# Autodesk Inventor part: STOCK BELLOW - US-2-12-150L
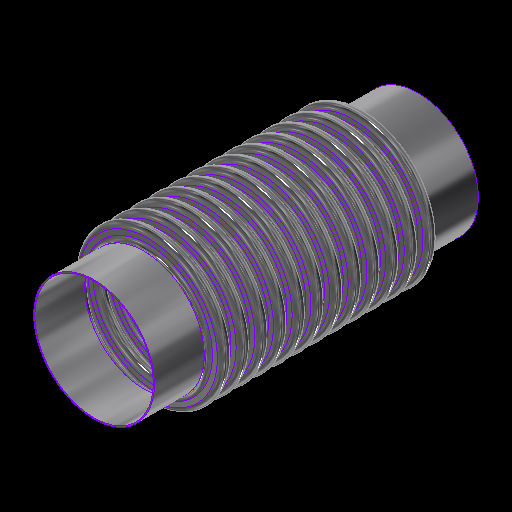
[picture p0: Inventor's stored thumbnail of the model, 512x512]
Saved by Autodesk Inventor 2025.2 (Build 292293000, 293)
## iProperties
Category: 24 GA (0.024 THICK)
RuleStatus: InUse
Created: 2024-01
Part Number: STOCK BELLOW - US-2-12-150L
Project: =STOCK BELLOWS: <Stock Number><SFILL>
Material: ASTM A240-304
Description: =STOCK BELLOWS: <Stock Number>, <SID_> I.D., <SOD_> O.D., <SPLY_> PLY, <Category>, <SNET_CONS> CONS.<PITCH_><STANGENT_> TANGENT<SFILL>
Document SubType Name: Sheet Metal
Designer: GS
Stock Number: U.S-2-12-150L
Surface Area: 1235.64 cm^2
Volume: 37.4488 cm^3
Sheet Metal Rule: Default
Appearance: STAINLESS STEEL
Mass: 301.736 g
Density: 8.05729 g/cm^3
THK: 0.036
ID: 3.500
OD: 4.250
CONS_: 2
PITCH: 0.500
TANGENT: 0.500
BELLOWS_UPSET: 0.000
d79: 1.000
d82: 1.000
d83: 26.000
d84: 24.000
d174: 8
d214: 8
STHK_: 0.024
SID_: 2.375
SOD_: 3.000
SPITCH_: 0.375
STANGENT__: 1.000
SBELLOWS_UPSET_: 0.000
SDIFF_TAN: 1.000
d252: 2
d275: 2
d287: 0.050
d289: 0.500
d290: 0.000
SOD_NECK: 2 7/16
PLY: 1
PSET: 4.178
PBAR: 1.035
COUNTER: 1.500
NET_TUBE: 3.071
CONS: 2
S_CONS: 0
NET_CONS: 2
ID_M: 88.90 mm
OD_M: 107.95 mm
THK_M: 0.91 mm
ID_U: 3.500 in
OD_U: 4.250 in
THK_U: 0.036 in
TANGENT2: 0.500
TAN_TO_TAN: 1.000 in
d80: 2.571
d81: 10
SID: 2.375
SCONS_: 12
SPITCH: 0.250
STANGENT_: 1.000
SBELLOWS_UPSET: 0.000
SNET_CONS: 12
SS_CONS: 0
SCONS: 8
d190: 8
d191: 1
d192: 1
d193: 8
d194: 0
SIZE: 2.00
PRESSURE: 150
d230: 8
STANGENT: 4.000
SPLY_: 1
d233: 8
d234: 0
d263: 2
d265: 1
d268: 2
d269: 0
d286: 2
d288: 1
d291: 2
d292: 0
SREROLL: 0.750
BLETP: 1.000 ul
PRES_Copy: 85
MATTABLE: 20 GA (0.036 THICK)
PART_NUMBER: U.S-2-12-150L
PITCH_: =, <SPITCH_> PITCH,
CFILL: .
SFILL: .
MESH: ,
COMP: 0.51
EXT: 0.26
LAT: 0.28
ANG: 573
ASR: 1940
LSR: 934
ANSR: 28
PRES: 150
COMPM: 5.1
EXTM: 2.55
LATM: 2.80
ASRM: 339.752
PRESM: 10.342
LSRM: 163.571
ANSRM: 4.904
TEMPMIN: 20
TEMPMAX: 800
TEMPMINM: -7
TEMPMAXM: 427
WEIGHTM: 0.302
WEIGHT: 0.665
Author: GS
Keywords: 20 GA (0.036 THICK)
Comments: =STOCK BELLOW - <STOCK NUMBER>
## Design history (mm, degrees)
sketch "Sketch2"
  geometry: L1 (0, -177.245)-(0, 562.856) reference; L2 (45.364, 0)-(44.45, 0); L3 (48.082, -2.718)-(50.343, -2.718); L4 (48.082, -3.632)-(50.343, -3.632); L5 (50.343, -9.982)-(48.082, -9.982); L6 (50.343, -9.068)-(48.082, -9.068); L7 (45.364, -12.7)-(44.45, -12.7); L8 (48.082, 0)-(48.082, -12.7); L9 (50.343, -6.35)-(53.975, -6.35); L10 (44.45, 0)-(44.45, -12.7); L11 (20.376, 102.841)-(20.376, 101.926); L12 (58.262, 457.127)-(58.262, 349.177); L13 (58.262, 444.427)-(58.262, 336.477); L14 (93.133, -58.817)-(93.133, -71.517); L15 (118.746, -66.401)-(118.746, -66.401); L16 (50.343, -9.068)-(50.343, -9.982); L17 (48.082, -9.068)-(48.082, -9.982); L18 (48.082, -9.525)-(50.343, -9.525); L19 (53.975, 0)-(53.975, -12.7); L20 (-50.343, -9.068)-(-50.343, -9.982); L21 (-50.343, -2.718)-(-48.082, -2.718); L22 (-50.343, -3.632)-(-48.082, -3.632); L23 (-48.082, -9.068)-(-50.343, -9.068); L24 (-50.343, -9.525)-(-48.082, -9.525); L25 (-48.082, -9.982)-(-50.343, -9.982); L26 (-48.082, -9.068)-(-48.082, -9.982); L27 (-44.45, 0.653)-(-44.45, -12.047); L28 (-48.082, -6.35)-(-44.45, -6.35); L29 (-50.343, 0.653)-(-50.343, -12.7); L30 (-53.061, 0)-(-53.975, 0); L31 (-53.975, 0)-(-53.975, -12.7); L32 (-53.061, -12.7)-(-53.975, -12.7); A1 r 2.718 centre (48.082, 0) between (45.364, 0) and (48.082, -2.718); A2 r 3.632 centre (48.082, 0) between (44.45, 0) and (48.082, -3.632); A3 r 3.632 centre (50.343, -6.35) between (50.343, -9.982) and (50.343, -2.718); A4 r 2.718 centre (50.343, -6.35) between (50.343, -9.068) and (50.343, -3.632); A5 r 2.718 centre (48.082, -12.7) between (48.082, -9.982) and (45.364, -12.7); A6 r 3.632 centre (48.082, -12.7) between (48.082, -9.068) and (44.45, -12.7); A7 r 3.175 centre (50.343, -6.35) between (50.343, -9.525) and (53.518, -6.35); A8 r 3.175 centre (48.082, -12.7) between (48.082, -9.525) and (44.907, -12.7); A9 r 2.718 centre (-50.343, -12.7) between (-50.343, -9.982) and (-53.061, -12.7); A10 r 2.718 centre (-48.082, -6.35) between (-48.082, -9.068) and (-48.082, -3.632); A11 r 3.175 centre (-48.082, -6.35) between (-48.082, -9.525) and (-44.907, -6.35); A12 r 3.632 centre (-48.082, -6.35) between (-48.082, -9.982) and (-48.082, -2.718); A13 r 3.175 centre (-50.343, -12.7) between (-50.343, -9.525) and (-53.518, -12.7); A14 r 3.632 centre (-50.343, -12.7) between (-50.343, -9.068) and (-53.975, -12.7); A15 r 2.718 centre (-50.343, 0) between (-53.061, 0) and (-50.343, -2.718); A16 r 3.632 centre (-50.343, 0) between (-53.975, 0) and (-50.343, -3.632); 10 further points
  constraints: 62 end point, 38 point on circle, 20 tangent, 16 centre point, 12 parallel, 9 midpoint, 7 vertical, 6 coincident, 6 concentric, 6 point on line, 4 equal radius, 4 perpendicular, 3 horizontal, 1 collinear, 1 horizontal alignment, 10 other
  dimensions: "THK" = 0.9144 distance of L11.start L11.end; "ID" = 88.9 distance of L11.end point (20.376, 13.026); "OD" = 107.95 distance of L12.start L12.end; "PITCH" = 12.7 distance of L12.start L13.start; "TANGENT" = 12.7 distance of L14.start L14.end; "BELLOWS_UPSET" = 0 distance of L15.start L15.end; "d43" = 88.9 diameter of L10 L1 (= ID); "d44" = 107.95 diameter of L9.end L1 (= OD); "d45" = 0.9144 distance between parallel lines of L5 L6 (computed from THK, PLY); "d46" = 3.6322 radius of A3 (computed from PITCH, THK, PLY); "UPSET_PITCH" = 12.7 distance of L2.end L7.end (derived); "SIDEWALL_ANGLE" = 360 deg dimension on L3 L9 (derived); "CON_GAP" = 5.4356 distance of point (48.082, -9.068) point (48.082, -3.632) (derived); "TAN1" = 4.98728 dimension on A8 (derived); "TAN2" = 4.98728 dimension on A7 (derived); "LEG1" = 2.2606 distance of L18.start L18.end (derived); "d278" = 0.9144 distance between parallel lines of L25 L23 (derived); "d279" = 3.6322 radius of A12 (derived); "d280" = 12.7 distance of L30.end L31.end (derived); "d281" = 360 deg dimension on L21 L28 (derived); "d282" = 5.4356 distance of point (-50.343, -9.068) point (-50.343, -3.632) (derived); "d283" = 4.98728 dimension on A13 (derived); "d284" = 4.98728 dimension on A11 (derived); "d285" = 2.2606 distance of L24.start L24.end (derived); "d293" = 88.9 diameter of L27 L1 (derived); "d294" = 107.95 diameter of L31 L1 (derived)
  node "Sketch Rectangular Pattern1" dims "d31" = 25.4, "ID" = 88.9
  node "Sketch Rectangular Pattern2" dims "d39" = 25.4, "PITCH" = 12.7
revolve "CONS" stored, may be unused: angle "d48" = 90 deg
node "BELLOW MIDPLANE"
pattern_linear "Rectangular Pattern2" dims "d52" = 12.7 (= UPSET_PITCH)
sketch "Sketch5"
  geometry: C1 r 45.364 at (0, 0) reference; C2 r 44.45 at (0, 0) reference
extrude "TANGENT" new body sketch "Sketch5" distance "d53" = 12.7 (= TANGENT); taper "d54" = 0 deg
revolve "SAMETAN" stored, may be unused: angle "d65" = 90 deg
revolve "DIFFTAN" stored, may be unused: angle "d70" = 90 deg
sketch "Sketch9"
  geometry: L1 (53.319, 0)-(-53.319, 0) reference; L2 (0, -17.78)-(0, 17.78) reference; L3 (38.085, 0)-(-38.085, 0); L4 (38.085, -11.906)-(38.085, 11.906); L5 (25.385, -11.906)-(25.385, 11.906); L6 (13.15, 11.906)-(13.15, -11.906); L7 (-25.385, -11.906)-(-25.385, 11.906); L8 (-38.085, -11.906)-(-38.085, 11.906); L9 (37.291, -11.906)-(37.291, 11.906); L10 (38.085, -11.906)-(37.291, -11.906); L11 (38.085, 11.906)-(37.291, 11.906); L12 (13.546, 11.906)-(12.753, 11.906); L13 (12.753, 11.906)-(12.753, -11.906); L14 (12.753, -11.906)-(13.546, -11.906); L15 (13.546, -11.906)-(13.546, 11.906); L16 (-13.546, 11.906)-(-13.546, -11.906); L17 (-13.15, 11.906)-(-13.15, -11.906); L18 (-13.546, -11.906)-(-12.753, -11.906); L19 (-12.753, -11.906)-(-12.753, 11.906); L20 (-12.753, 11.906)-(-13.546, 11.906); L21 (-38.085, -11.906)-(-37.291, -11.906); L22 (-37.291, -11.906)-(-37.291, 11.906); L23 (-37.291, 11.906)-(-38.085, 11.906); L24 (-38.085, 11.906)-(-38.085, -11.906); L25 (38.085, -0.397)-(-38.085, -0.397); L26 (-38.085, -0.397)-(-38.085, 0.397); L27 (-38.085, 0.397)-(38.085, 0.397); L28 (38.085, 0.397)-(38.085, -0.397); L29 (-38.085, 11.906)-(38.085, 11.906); L30 (38.085, 11.906)-(38.085, 12.7); L31 (38.085, 12.7)-(-38.085, 12.7); L32 (-38.085, 12.7)-(-38.085, 11.906); L33 (38.085, -11.906)-(-38.085, -11.906); L34 (-38.085, -11.906)-(-38.085, -12.7); L35 (-38.085, -12.7)-(38.085, -12.7); L36 (38.085, -12.7)-(38.085, -11.906); 30 further points
  constraints: 68 end point, 13 midpoint, 13 parallel, 8 horizontal, 7 perpendicular, 6 equal length, 3 point on line, 2 vertical, 14 other
  dimensions: "d115" = 23.8125 distance of L4.start L4.end (derived); "d116" = 12.7 distance between parallel lines of L4 L5 (derived); "d117" = 12.23516 distance between parallel lines of L5 L6 (derived); "d125" = 38.53427 distance between parallel lines of L7 L6 (derived); "d127" = 12.7 distance between parallel lines of L8 L7 (derived); "d128" = 24.93516 distance between parallel lines of L6 L4 (derived); "d130" = 76.16943 distance between parallel lines of L8 L4 (derived); "RULER_THK" = 0.79375 distance between parallel lines of L4 L9; "d135" = 0.79375 distance of L13.end L14.end (derived); "d138" = 26.29911 distance of L13.end L16.end (derived); "d143" = 0.79375 distance of L22.end L8.end (derived); "d144" = 0.79375 distance between parallel lines of L27 L25 (derived)
extrude "RULER" join sketch "Sketch9" distance "d149" = 0.79375 (derived); taper "d150" = 0 deg
extrude "BARS" join sketch "Sketch9" distance "d151" = 0.79375 (derived); taper "d152" = 0 deg
pattern_linear "Rectangular Pattern4" dims "d155" = 26.29911 (derived)
sketch "Sketch13"
  geometry: L1 (93.149, -52.467)-(93.149, -77.867); L2 (30.772, 0)-(30.162, 0); L3 (30.772, -9.525)-(30.162, -9.525); L4 (35.414, -7.449)-(32.849, -7.449); L5 (35.414, -6.839)-(32.849, -6.839); L6 (35.414, -4.763)-(38.1, -4.762); L7 (32.849, -2.076)-(35.414, -2.076); L8 (32.849, 0)-(32.849, -9.525); L9 (30.162, 0)-(30.162, -9.525); L10 (58.254, -420.231)-(58.254, -496.431); L11 (58.254, -429.756)-(58.254, -505.956); L12 (58.254, -448.806)-(58.254, -525.006); L13 (58.254, -458.331)-(58.254, -534.531); L14 (58.254, -467.856)-(58.254, -544.056); L15 (58.254, -477.381)-(58.254, -553.581); L16 (58.254, -486.906)-(58.254, -563.106); L17 (58.254, -439.281)-(58.254, -515.481); L18 (20.376, 102.536)-(20.376, 101.926); L19 (32.849, -2.686)-(35.414, -2.686); L20 (0, -696.234)-(0, 235.664) reference; L21 (-23.752, 0)-(142.514, 0) reference; A1 r 2.076 centre (32.849, 0) between (30.772, 0) and (32.849, -2.076); A2 r 2.076 centre (32.849, -9.525) between (32.849, -7.449) and (30.772, -9.525); A3 r 2.686 centre (32.849, -9.525) between (32.849, -6.839) and (30.162, -9.525); A4 r 2.076 centre (35.414, -4.763) between (35.414, -6.839) and (35.414, -2.686); A5 r 2.686 centre (35.414, -4.763) between (35.414, -7.449) and (35.414, -2.076); A6 r 2.686 centre (32.849, 0) between (30.162, 0) and (32.849, -2.686); 6 further points; 1 other entity
  constraints: 38 end point, 15 point on circle, 9 tangent, 6 centre point, 6 parallel, 5 vertical alignment, 4 point on line, 4 vertical, 3 coincident, 3 concentric, 2 collinear, 2 equal radius, 1 horizontal, 1 perpendicular, 23 other
  dimensions: "SBELLOWS_UPSET_" = 0 distance of point (118.762, -66.401) point (118.762, -66.401); "STOTAL_THK_BELLOW__" = 0.6096 distance between parallel lines of L4 L5 (derived); "d224" = 2.68605 radius of A5 (derived); "d225" = 9.525 distance of L2.end L3.end (derived); "SSIDEWALL_ANGLE_" = 0 deg angle of L7 L6 (derived); "SSCON_GAP_" = 4.1529 distance of point (32.849, -6.839) point (32.849, -2.686) (derived); "d235" = 60.325 diameter of L9 L20 (derived); "d236" = 76.2 diameter of L6.end L20 (derived)
  node "Sketch Rectangular Pattern4" dims "d228" = 25.4
  node "Sketch Rectangular Pattern5" dims "d229" = 25.4
revolve "SBELLOW" stored, may be unused: angle "d197" = 90 deg
pattern_linear "Rectangular Pattern5" dims "d204" = 9.525 (derived)
revolve "STANGENT" stored, may be unused: angle "d240" = 90 deg
revolve "SSAMETAN" stored, may be unused: angle "d241" = 90 deg
revolve "SDIFFTAN" stored, may be unused: angle "d246" = 90 deg
revolve "INVCON" stored, may be unused: angle "d295" = 90 deg
pattern_linear "Rectangular Pattern6" dims "d298" = 12.7 (derived)
revolve "INVTANGENT" stored, may be unused: angle "d302" = 90 deg
revolve "INVSAMETAN" stored, may be unused: angle "d307" = 90 deg
revolve "INVDIFFTAN" stored, may be unused: angle "d312" = 90 deg
sketch "ID BELLOW MOUNT CALC"
  geometry: L1 (44.45, 0)-(38.1, 0); L2 (38.1, 0)-(38.1, 12.7); L3 (38.1, 12.7)-(44.45, 12.7); L4 (44.45, 12.7)-(44.45, 0); L5 (36.513, 12.7)-(35.598, 12.7); L6 (35.598, 12.7)-(35.598, 0); L7 (35.598, 0)-(36.513, 0); L8 (36.513, 0)-(36.513, 12.7); L9 (0, -2.54)-(0, 15.24) reference; L10 (-8.89, 0)-(53.34, 0) reference; 1 further point
  constraints: 16 end point, 5 parallel, 2 collinear, 2 horizontal, 2 perpendicular
  dimensions: "d314" = 12.7 distance of L5.end L6.end (derived); "d315" = 0.9144 distance of L5.start L5.end (derived); "IG" = 1.5875 distance between parallel lines of L2 L8; "PIPE_OD" = 88.9 diameter of L4 L9; "PIPE_WALL" = 6.35 distance of L2.end L3.end; "ID_MT_BELLOW" = 71.1962 diameter of L6 L9 (derived)
revolve "CFILL" stored, may be unused: angle "d320" = 90 deg
pattern_linear "Rectangular Pattern7" dims "d323" = 12.7 (derived)
revolve "SFILL" stored, may be unused: angle "d324" = 90 deg
pattern_linear "Rectangular Pattern8" dims "d327" = 9.525 (derived)
node "STOCK BELLOW MIDPLANE"
node "BELLOW"
sketch "Sketch6"
  geometry: L1 (-12.7, 45.364)-(0, 45.364); L2 (0, 45.364)-(0, 44.45); L3 (0, 44.45)-(-12.7, 44.45); L4 (-12.7, 44.45)-(-12.7, 45.364); L5 (10.16, 0)-(-60.96, 0) reference; L6 (-38.1, -89.422)-(-38.1, 153.44) reference; 1 further point
  constraints: 8 end point, 2 parallel, 1 horizontal, 1 perpendicular
  dimensions: "d61" = 12.7 distance of L2.end L3.end (derived); "d62" = 0.9144 distance of L1.end L2.end (derived); "d63" = 88.9 diameter of L3 L5 (derived); "d64" = 25.4 distance between parallel lines of L4 L6 (derived)
sketch "Sketch12"
  geometry: 1 further point
sketch "Sketch14"
  geometry: L1 (-25.4, 30.772)-(0, 30.772); L2 (0, 30.772)-(0, 30.162); L3 (0, 30.162)-(-25.4, 30.162); L4 (-25.4, 30.162)-(-25.4, 30.772); L5 (5.08, 0)-(-30.48, 0) reference; L6 (0, -8.89)-(0, 53.34) reference; 1 further point
  constraints: 8 end point, 2 parallel, 1 collinear, 1 horizontal, 1 perpendicular
  dimensions: "d237" = 0.6096 distance of L3.end L1.start (derived); "d238" = 60.325 diameter of L3 L5 (derived); "d239" = 25.4 distance of L1.start L1.end (derived); "SOD_NECK" = 61.5442 diameter of L1 L5 (derived)
sketch "Sketch15"
  geometry: L1 (-8.89, 0)-(53.34, 0) reference; L2 (30.163, -114.3)-(30.772, -114.3); L3 (30.772, -114.3)-(30.772, -139.7); L4 (30.772, -139.7)-(30.163, -139.7); L5 (30.163, -139.7)-(30.163, -114.3); L6 (0, -170.18)-(0, 43.18) reference; 1 further point
  constraints: 8 end point, 2 parallel, 1 horizontal, 1 perpendicular
  dimensions: "d205" = 25.4 distance of L4.end L2.start (derived); "d206" = 0.6096 distance of L3.end L4.end (derived); "d207" = 60.325 diameter of L5 L6 (derived); "d208" = 114.3 distance between parallel lines of L1 L2 (derived)
node "TANGENT_"
node "SAME_TAN"
sketch "Sketch8"
  geometry: L1 (45.364, -25.4)-(44.45, -25.4); L2 (44.45, -25.4)-(44.45, -38.1); L3 (44.45, -38.1)-(45.364, -38.1); L4 (45.364, -38.1)-(45.364, -25.4); L5 (0, -48.26)-(0, 22.86) reference; L6 (-89.422, 0)-(153.44, 0) reference; 1 further point
  constraints: 8 end point, 2 parallel, 1 horizontal, 1 perpendicular
  dimensions: "d66" = 88.9 diameter of L2 L5 (derived); "TOTAL_THK_BELLOW" = 0.9144 distance of L2.end L3.end (derived); "d68" = 25.4 distance between parallel lines of L1 L6 (derived); "d69" = 12.7 distance of L1.end L2.end (derived)
node "DIFF_TAN"
node "Sketch Rectangular Pattern3" dims "d138" = 26.29911 (derived), "d141" = 25.4
node "SBELLOW_"
node "STANGENT_"
node "SSAME_TAN"
sketch "Sketch16"
  geometry: L1 (30.772, -114.3)-(30.163, -114.3); L2 (30.163, -114.3)-(30.163, -139.7); L3 (30.163, -139.7)-(30.772, -139.7); L4 (30.772, -139.7)-(30.772, -114.3); L5 (0, -170.18)-(0, 43.18) reference; L6 (-8.89, 0)-(53.34, 0) reference; 1 further point
  constraints: 8 end point, 2 parallel, 1 horizontal, 1 perpendicular
  dimensions: "SDIFF_TAN" = 25.4 distance of L3.end L1.start; "d243" = 0.6096 distance of L2.end L3.end (derived); "d244" = 114.3 distance between parallel lines of L1 L6 (derived); "d245" = 60.325 diameter of L2 L5 (derived)
node "SDIFF_TAN"
body "Solid15"
sketch "Sketch17"
  geometry: L1 (53.975, 12.7)-(53.061, 12.7); L2 (53.061, 12.7)-(53.061, 0); L3 (53.061, 0)-(53.975, 0); L4 (53.975, 0)-(53.975, 12.7); L5 (0, -2.54)-(0, 15.24) reference; L6 (-10.795, 0)-(64.77, 0) reference; 2 further points
  constraints: 8 end point, 2 parallel, 1 horizontal, 1 midpoint, 1 perpendicular, 1 point on line
  dimensions: "INVTANGENT" = 12.7 distance of L3.end L1.start (derived); "d300" = 0.9144 distance of L1.start L1.end (derived); "d301" = 107.95 diameter of L4 L5 (derived)
body "Solid16"
sketch "Sketch18"
  geometry: L1 (53.975, -25.4)-(53.061, -25.4); L2 (53.061, -25.4)-(53.061, -38.1); L3 (53.061, -38.1)-(53.975, -38.1); L4 (53.975, -38.1)-(53.975, -25.4); L5 (-10.795, 0)-(64.77, 0) reference; L6 (0, -48.26)-(0, 22.86) reference; 1 further point
  constraints: 8 end point, 2 parallel, 1 horizontal, 1 perpendicular
  dimensions: "d303" = 25.4 distance between parallel lines of L1 L5 (derived); "d304" = 12.7 distance of L3.end L1.start (derived); "d305" = 0.9144 distance of L2.end L3.end (derived); "d306" = 107.95 diameter of L4 L6 (derived)
body "Solid17"
sketch "Sketch19"
  geometry: L1 (53.975, -25.4)-(53.061, -25.4); L2 (53.061, -25.4)-(53.061, -38.1); L3 (53.061, -38.1)-(53.975, -38.1); L4 (53.975, -38.1)-(53.975, -25.4); L5 (0, -48.26)-(0, 22.86) reference; L6 (-10.795, 0)-(64.77, 0) reference; 1 further point
  constraints: 8 end point, 2 parallel, 1 horizontal, 1 perpendicular
  dimensions: "d308" = 12.7 distance of L1.end L2.end (derived); "d309" = 107.95 diameter of L4 L5 (derived); "d310" = 0.9144 distance of L2.end L3.end (derived); "d311" = 25.4 distance between parallel lines of L1 L6 (derived)
body "Solid18"
body "Solid19"
body "Solid20"
other parameters: "BMPL" = -57.15, "PSET" = 106.1212 (computed from OD, THK, PLY) [user parameter], "PBAR" = 26.29911 (= 0.570796 x PITCH + OD - ID) [user parameter; used in 1 equation term], "COUNTER" = 15 [user parameter], "NET_TUBE" = 77.99823 (computed from CONS_, PBAR, TANGENT) [user parameter], "S_CONS" = 0 [user parameter; used in 1 equation term], "ID_M" = 88.9 (= ID) [user parameter], "OD_M" = 107.95 (= OD) [user parameter], "THK_M" = 0.9144 (= THK) [user parameter], "ID_U" = 88.9 (= ID) [user parameter], "OD_U" = 107.95 (= OD) [user parameter], "THK_U" = 0.9144 (= THK) [user parameter], "D_UNITS" = 0 [user parameter], "TANGENT2" = 12.7 [user parameter], "TAN_TO_TAN" = 25.4 [user parameter], "OD_NECK" = 90.7288 [user parameter], "d79" = 25.4, "d80" = 65.29823 [user parameter], "d82" = 25.4, "d83" = 660.4, "d84" = 609.6, "sa_0" = 4, "FRAME_THK" = 0.79375 [user parameter], "CON_FLAT" = 12.23516 [user parameter], "SID" = 60.325 [user parameter], "SPITCH" = 6.35 [user parameter], "STANGENT_" = 25.4 [user parameter], "SBELLOWS_UPSET" = 0 [user parameter], "SS_CONS" = 0 [user parameter], "STAN_TO_TAN_" = 114.3 [user parameter], "d100" = 0.6096 [user parameter], "d191" = 25.4 [user parameter], "d194" = 0 [user parameter], "STANGENT" = 101.6 [user parameter], "d234" = 0 [user parameter], "SUPSET_PITCH_" = 9.525 [user parameter], "d269" = 0 [user parameter], "d287" = 1.27, "d289" = 12.7, "d290" = 0, "d292" = 0 [user parameter], "Thickness" = 3.048 (derived), "KFactor" = 4.4, "BendRadius" = 3.048 (derived), "BendReliefWidth" = 3.048 (derived), "BendReliefDepth" = 1.524 (derived), "CornerReliefSize" = 12.192 (derived), "SeamGap" = 0.00508, "MinimumRemnant" = 6.096 (derived), "TransitionRadius" = 3.048 (derived), "JacobiRadiusSize" = 3.048 (derived), "GapSize" = 3.048 (derived), "SREROLL" = 19.05 [user parameter], "CUR_STK_PITCH" = 9.525 [user parameter], "d328" = -57.15 (derived), "ASR" = 19400 [user parameter], "BLETP" = 1 [user parameter], "ASRM" = 3397.522 [user parameter], "PRESM" = 103.41975 [user parameter], "LSRM" = 1635.7142 [user parameter], "ANSRM" = 49.0364 [user parameter], "TEMPMIN" = 2664.83333 [user parameter], "TEMPMAX" = 6998.16667 [user parameter], "TEMPMINM" = 2664.83333 [user parameter], "TEMPMAXM" = 6998.16667 [user parameter], "WEIGHT" = 3.01736 [user parameter], "WEIGHTM" = 0.00302 [user parameter]
